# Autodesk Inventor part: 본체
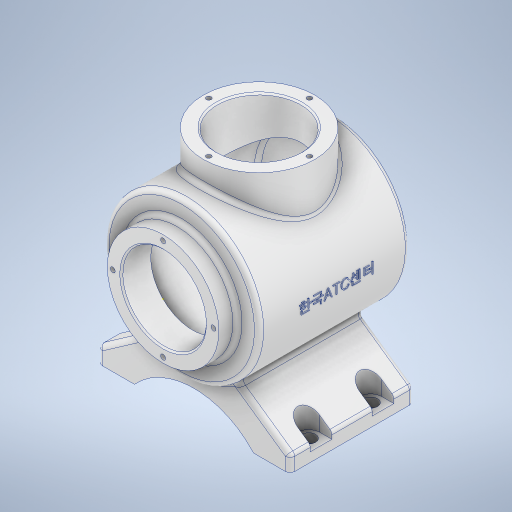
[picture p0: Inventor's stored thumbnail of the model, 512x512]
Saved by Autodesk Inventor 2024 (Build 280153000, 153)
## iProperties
Created: 2023-08
Part Number: 본체
Material: 알루미늄 6061
Document SubType Name: Modeling
Designer: Owner
Density: 2.7 g/cm^3
Appearance: 알루미늄 - 평지
Mass: 1295.73 g
Surface Area: 1062.7 cm^2
Volume: 479.901 cm^3
Author: Owner
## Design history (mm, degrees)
sketch "스케치1"
  geometry: L1 (0, 0)-(0, -120); L2 (27, 0)-(27, -19); L3 (27, -19)-(40, -19); L4 (43, -22)-(43, -101.916); L5 (27, 0)-(36, 0); L6 (36, 0)-(36, -12); L7 (36, -12)-(47, -12); L8 (50, -15)-(50, -106.454); A1 r 106 centre (0, -7) between (0, -113) and (41.165, -104.68); A2 r 113 centre (0, -7) between (0, -120) and (48.282, -109.166); A3 r 3 centre (47, -15) between (50, -15) and (47, -12); A4 r 3 centre (40, -22) between (43, -22) and (40, -19); A5 r 3 centre (47, -106.454) between (48.282, -109.166) and (50, -106.454); A6 r 3 centre (40, -101.916) between (41.165, -104.68) and (43, -101.916); 2 further points
  constraints: 16 end point, 14 point on circle, 8 tangent, 6 centre point, 5 perpendicular, 4 point on line, 3 equal radius, 2 vertical, 1 horizontal
  dimensions: "d1" = 120 distance of L1.start L1.end; "d2" = 113 radius of A2; "d3" = 7 radial gap between concentric circles of A2 A1; "d4" = 108 distance from line of L1.end L7; "d5" = 100 diameter of L8 L1; "d6" = 86 diameter of L4 L1; "d7" = 54 diameter of L2 L1; "d8" = 120 distance from line of L1.end L5; "d9" = 72 diameter of L6 L1; "d10" = 19 distance between parallel lines of L3 L5; "d11" = 3 radius of A3
revolve "회전1" sketch "스케치1" stored, may be unused: angle "d12" = 90 deg
node "작업 평면1"
sketch "스케치2"
  geometry: C1 r 36 at (0, -62); 1 further point
  constraints: 1 centre point, 1 vertical alignment
  dimensions: "d14" = 72 diameter of C1; "d15" = 62 distance of point (0, 0) C1.centre
extrude "돌출1" join sketch "스케치2" stored distance "d16" = 10; taper "d17" = 0 deg
sketch "스케치3"
  geometry: C1 r 36 at (0, 0) reference; C2 r 27 at (0, 0); 1 further point
  constraints: 1 centre point, 1 coincident
  dimensions: "d18" = 54 diameter of C2
extrude "돌출2" cut sketch "스케치3" stored distance "d19" = 10; taper "d20" = 0 deg
chamfer "모따기1" distance "d21" = 1; stored, may be unused: second distance "d22" = 2, angle "d23" = 45 deg
fillet "모깎기1" dims "d24" = 3
sketch "스케치4"
  geometry: 1 further point
node "작업 평면2"
sketch "스케치5"
  geometry: L1 (26.694, -42.278)-(62, -67); L2 (62, -67)-(62, -77); L3 (62, -77)-(38.5, -77); L4 (-38.5, -77)-(-62, -77); L5 (-62, -77)-(-62, -67); L6 (-62, -67)-(-26.694, -42.278); A1 r 50 centre (0, 0) between (26.694, -42.278) and (-26.694, -42.278) reference; A2 r 52.096 centre (0, -112.096) between (38.5, -77) and (-38.5, -77); 2 further points
  constraints: 12 end point, 5 point on circle, 3 equal length, 2 perpendicular, 1 centre point, 1 collinear, 1 horizontal, 1 vertical
  dimensions: "d26" = 55 deg angle of L2 L1; "d27" = 55 deg angle of L5 L6; "d28" = 77 distance of L3.end L4.start; "d29" = 10 distance from line of L3 L1.end; "d30" = 17 distance from line of L3 point (0, -60); "d31" = 124 distance between parallel lines of L2 L5; "d32" = 77 distance from line of L3 point (0, 0)
extrude "돌출3" join sketch "스케치5" distance "d33" = 80; taper "d34" = 0 deg
fillet "모깎기2" dims "d35" = 3
fillet "모깎기3" dims "d36" = 3
node "작업 평면3"
sketch "스케치6"
  geometry: L1 (-23.5, 13)-(-15.5, 13); L2 (-15.5, 27)-(-23.5, 27); L3 (-23.5, 77)-(-23.5, 3) reference; L4 (0, 0)-(-20.5, 0) reference; L5 (-23.5, 40)-(105.381, 40); L6 (-23.5, 67)-(-15.5, 67); L7 (-15.5, 53)-(-23.5, 53); L8 (38.5, 100)-(38.5, -9.177); L9 (92.5, 27)-(100.5, 27); L10 (100.5, 13)-(92.5, 13); L11 (92.5, 53)-(100.5, 53); L12 (100.5, 67)-(92.5, 67); L13 (-23.5, 13)-(-23.5, 27); L14 (-23.5, 53)-(-23.5, 67); L15 (100.5, 13)-(100.5, 27); L16 (100.5, 77)-(100.5, 3) reference; L17 (100.5, 53)-(100.5, 67); A1 r 7 centre (-15.5, 20) between (-15.5, 13) and (-15.5, 27); A2 r 7 centre (-15.5, 60) between (-15.5, 53) and (-15.5, 67); A3 r 7 centre (92.5, 20) between (92.5, 27) and (92.5, 13); A4 r 7 centre (92.5, 60) between (92.5, 67) and (92.5, 53); 2 further points
  constraints: 28 end point, 15 symmetric about line, 8 point on circle, 4 centre point, 4 collinear, 2 horizontal, 2 point on line, 2 tangent, 1 midpoint, 1 parallel, 1 vertical, 3 other
  dimensions: "d38" = 14 distance between parallel lines of L2 L1; "d39" = 20 distance from line of L4 A1.centre; "d40" = 8 distance from line of L3 A1.centre
extrude "돌출4" cut sketch "스케치6" stored distance "d42" = 80; taper "d43" = 0 deg
sketch "스케치7"
  geometry: A1 r 7 centre (-15.5, -20) between (-15.5, -27) and (-15.5, -13) reference; A2 r 7 centre (-15.5, -60) between (-15.5, -67) and (-15.5, -53) reference; A3 r 7 centre (92.5, -20) between (92.5, -13) and (92.5, -27) reference; A4 r 7 centre (92.5, -60) between (92.5, -53) and (92.5, -67) reference; 5 further points
  constraints: 4 coincident
hole "구멍1" sketch "스케치7" at (-15.5, -20), (-15.5, -60), (92.5, -20), (92.5, -60) diameter "d44" = 9; stored, may be unused: countersink angle "d48" = 90 deg, drill point angle "d50" = 0 deg; dims "d45" = 6, "d46" = 4, "d47" = 2, "d49" = 8
node "작업 평면4"
sketch "스케치8"
  geometry: L1 (-36, 60.727)-(36, 60.727) reference; 3 further points
  constraints: 1 midpoint, 1 vertical alignment, 1 other
  dimensions: "d51" = 62 distance from line of L1 point (0, -1.273)
feature "엠보싱1" sketch "스케치8" dims "d52" = 0.5, "d53" = 0
sketch "스케치9"
  geometry: 5 further points
  constraints: 1 vertical alignment, 5 other
  dimensions: "d54" = 32.5 distance of point (0, 0) point (0, 32.5); "d57" = 360 deg dimension on point (0, 0) point (0, 32.5) (derived)
hole "구멍2" sketch "스케치9" at (-32.5, 0), (0, 32.5), (32.5, 0), (0, -32.5) diameter "d59" = 3.242; stored, may be unused: countersink angle "d63" = 90 deg, drill point angle "d65" = 118 deg; dims "d60" = 8, "d61" = 4, "d62" = 2, "d64" = 10
sketch "스케치10"
  geometry: C1 r 27 at (0, 0) reference; 5 further points
  constraints: 1 vertical alignment, 5 other
  dimensions: "d66" = 32.5 distance of C1.centre point (0, 32.5); "d69" = 360 deg dimension on C1.centre point (0, 32.5) (derived)
hole "구멍3" sketch "스케치10" at (-32.5, 0), (0, -32.5), (32.5, 0), (0, 32.5) diameter "d71" = 3.242; stored, may be unused: countersink angle "d75" = 90 deg, drill point angle "d77" = 118 deg; dims "d72" = 8, "d73" = 4, "d74" = 2, "d76" = 10
node "솔리드1"
feature "A9D066F2-1C7D-4E18-AEED-F7BC21143FA4" dims "d44" = 9, "d45" = 6, "d46" = 4, "d47" = 2, "d48" = 90 deg, "d49" = 8, "d50" = 0
other parameters: "d13" = 65, "d37" = -6
